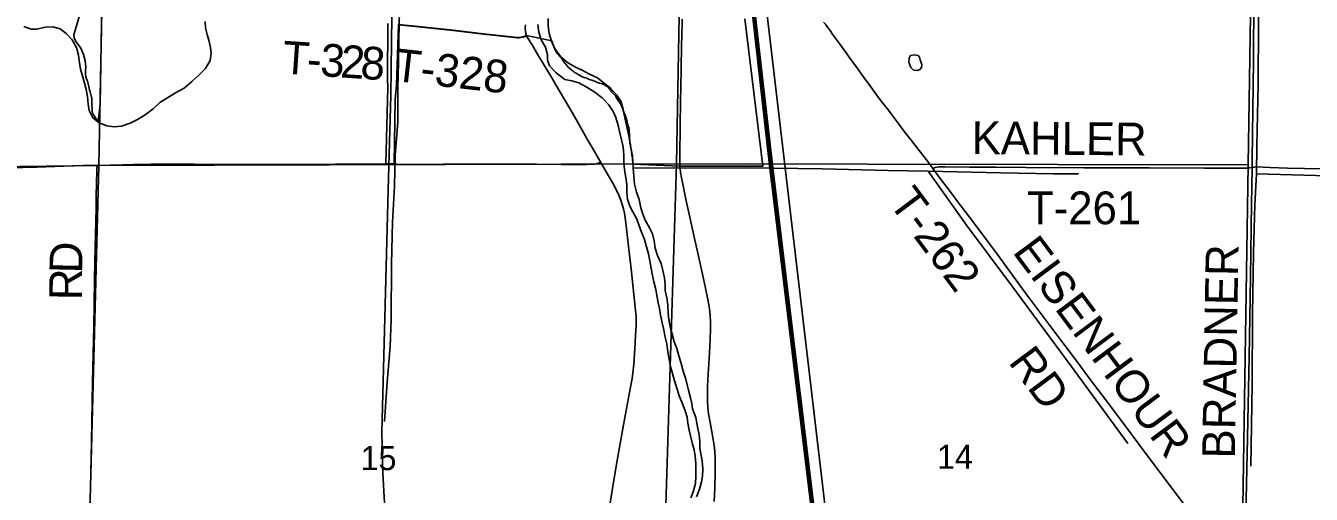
# Model space of a CAD drawing. Extents: x 0 to 34, y 0 to 22.
# Drawn here: x 3.939 to 6.172, y 15.963 to 16.776 of the extents above; entities that cross this region are included whole.
import ezdxf

# ---------------------------------------------------------------- set-up
doc = ezdxf.new("R2010")
doc.units = 0
for name, color, linetype in [('GM_X_Corporation', 7, 'Continuous'), ('GM_X_County_Road', 7, 'Continuous'), ('GM_X_Major_River', 7, 'Continuous'), ('GM_X_Minor_Lake', 7, 'Continuous'), ('GM_X_Minor_River', 7, 'Continuous'), ('GM_X_Rail_Line', 7, 'Continuous'), ('GM_X_Section', 7, 'Continuous'), ('GM_X_Section_Text', 7, 'Continuous'), ('GM_X_Township_Road', 7, 'Continuous'), ('GM_X_Township_Road_Text', 7, 'Continuous')]:
    doc.layers.add(name, color=color, linetype=linetype)

msp = doc.modelspace()

# ---------------------------------------------------------------- linework, layer by layer
at = {"layer": 'GM_X_Corporation'}
for points in [[(4.071, 16.8152), (4.0678, 16.6389), (4.0673, 16.6338), (4.0643, 16.6095), (4.0598, 16.6158), (4.0552, 16.6228), (4.0545, 16.6247), (4.054, 16.6272), (4.0539, 16.6297), (4.0537, 16.6409), (4.0532, 16.6505), (4.0531, 16.6519), (4.0504, 16.6611), (4.0493, 16.6649), (4.0458, 16.6802), (4.0454, 16.681), (4.0446, 16.6828), (4.0439, 16.685), (4.0436, 16.6857), (4.0432, 16.6872), (4.0431, 16.6879), (4.0428, 16.6891), (4.0426, 16.6913), (4.0425, 16.6929), (4.0425, 16.6948), (4.0426, 16.6967), (4.0427, 16.6974), (4.0429, 16.7043), (4.0419, 16.7148), (4.0391, 16.7258), (4.0342, 16.737), (4.0265, 16.7481), (4.0233, 16.753), (4.0226, 16.7547), (4.0222, 16.7599), (4.0326, 16.7955)], [(5.1883, 16.7876), (5.2193, 16.5319), (5.0752, 16.5321), (4.9943, 16.5359), (4.9931, 16.5431), (4.9928, 16.5475), (4.9928, 16.5514), (4.9921, 16.5538), (4.9916, 16.5566), (4.9904, 16.5611), (4.9893, 16.5668), (4.9893, 16.5689), (4.9884, 16.5718), (4.9871, 16.5956), (4.9866, 16.5986), (4.9845, 16.605), (4.9836, 16.6098), (4.9817, 16.6154), (4.9803, 16.6207), (4.9781, 16.6259), (4.9768, 16.6286), (4.9765, 16.6297), (4.9758, 16.6321), (4.973, 16.6386), (4.9726, 16.6399), (4.9712, 16.642), (4.9706, 16.6432), (4.9694, 16.6446), (4.9672, 16.6475), (4.9653, 16.6503), (4.9638, 16.6534), (4.9619, 16.656), (4.9586, 16.659), (4.957, 16.6607), (4.9563, 16.662), (4.9532, 16.6662), (4.9507, 16.669), (4.95, 16.6697), (4.947, 16.6712), (4.9465, 16.6716), (4.9459, 16.6721), (4.9437, 16.6737), (4.9428, 16.6742), (4.942, 16.6745), (4.9408, 16.675), (4.9383, 16.6757), (4.9358, 16.6763), (4.9306, 16.6782), (4.9285, 16.6791), (4.9224, 16.6814), (4.9178, 16.6827), (4.9136, 16.6846), (4.9091, 16.6858), (4.9056, 16.687), (4.9038, 16.6883), (4.8986, 16.6911), (4.8969, 16.6925), (4.8949, 16.6935), (4.8917, 16.6953), (4.8896, 16.6968), (4.882, 16.7031), (4.8734, 16.7133), (4.8706, 16.7177), (4.8683, 16.7213), (4.8677, 16.7218), (4.8668, 16.7226), (4.8656, 16.724), (4.8635, 16.7264), (4.8617, 16.7285), (4.8602, 16.7309), (4.8598, 16.7318), (4.859, 16.7337), (4.8577, 16.7365), (4.8566, 16.739), (4.8564, 16.7397), (4.8562, 16.7404), (4.8557, 16.7417), (4.8547, 16.7434), (4.8544, 16.744), (4.8539, 16.7468), (4.8535, 16.7477), (4.8532, 16.7484), (4.8532, 16.7488), (4.853, 16.7495), (4.8086, 16.759), (4.8059, 16.7576), (4.8028, 16.7565), (4.7987, 16.7559), (4.7956, 16.7555), (4.7925, 16.7556), (4.7878, 16.7559), (4.7338, 16.762), (4.6813, 16.7679), (4.6211, 16.7743), (4.5862, 16.7781), (4.5828, 16.6728), (4.5805, 16.6481), (4.5787, 16.536), (4.5643, 16.5361), (4.5678, 16.6686), (4.5674, 16.6831), (4.5681, 16.78)]]:
    msp.add_lwpolyline(points, dxfattribs=at)
at = {"layer": 'GM_X_County_Road'}
for points in [[(4.8088, 16.7585), (4.8076, 16.7623), (4.8068, 16.7665), (4.8066, 16.7698), (4.8066, 16.7728), (4.8072, 16.7774)], [(5.0755, 16.5315), (5.0754, 16.5372), (5.0752, 16.5474), (5.0758, 16.6049), (5.0764, 16.6422), (5.0773, 16.6997), (5.0783, 16.7433), (5.0786, 16.7573), (5.0794, 16.7837), (5.0794, 16.787)], [(4.9378, 16.5386), (4.9228, 16.5645), (4.9142, 16.5793), (4.8972, 16.6089), (4.8926, 16.617), (4.8857, 16.6291), (4.8731, 16.6505), (4.8597, 16.6733), (4.8527, 16.6854), (4.8465, 16.6961), (4.836, 16.7134), (4.8303, 16.7226), (4.8239, 16.7332), (4.8207, 16.7386), (4.8185, 16.7425), (4.816, 16.7465), (4.8143, 16.749), (4.812, 16.7525), (4.81, 16.7558), (4.8088, 16.7585)], [(4.9539, 15.9482), (4.9617, 15.9942), (4.967, 16.0248), (4.9713, 16.0509), (4.9777, 16.0861), (4.9845, 16.1212), (4.9897, 16.1487), (4.9923, 16.164), (4.9941, 16.1779), (4.9952, 16.1888), (4.9969, 16.2152), (4.9983, 16.2385), (4.9993, 16.2556), (4.9994, 16.2634), (4.9992, 16.2712), (4.9983, 16.2821), (4.9943, 16.3207), (4.9913, 16.3486), (4.9855, 16.398), (4.9826, 16.4242), (4.9809, 16.4382), (4.979, 16.4505), (4.9775, 16.4581), (4.9753, 16.4657), (4.9727, 16.4731), (4.9691, 16.4817), (4.9645, 16.4916), (4.9594, 16.5013), (4.9384, 16.5376), (4.9378, 16.5386)], [(5.1346, 15.95), (5.1359, 15.9732), (5.1368, 15.9996), (5.1369, 16.0136), (5.1366, 16.026), (5.136, 16.0368), (5.1348, 16.0475), (5.1325, 16.0613), (5.1277, 16.0873), (5.1253, 16.1026), (5.124, 16.1135), (5.1233, 16.1244), (5.1231, 16.1353), (5.1233, 16.1509), (5.1242, 16.1711), (5.1265, 16.2083), (5.1278, 16.2315), (5.1285, 16.2501), (5.1286, 16.2625), (5.1282, 16.2718), (5.1275, 16.2795), (5.1262, 16.2887), (5.1234, 16.3039), (5.1199, 16.3206), (5.1145, 16.3449), (5.1063, 16.3812), (5.0995, 16.4116), (5.0927, 16.4435), (5.0865, 16.4723), (5.081, 16.4982), (5.0781, 16.5119), (5.0765, 16.5211), (5.0756, 16.5289), (5.0755, 16.5315)]]:
    msp.add_lwpolyline(points, dxfattribs=at)
at = {"layer": 'GM_X_Major_River'}
for points in [[(4.2504, 16.7831), (4.2509, 16.7724), (4.254, 16.7606), (4.2568, 16.751), (4.2599, 16.738), (4.2608, 16.7285), (4.2593, 16.7157), (4.251, 16.7014), (4.2398, 16.6907), (4.2274, 16.6792), (4.2138, 16.6674), (4.1989, 16.6594), (4.1719, 16.6426), (4.1603, 16.6319), (4.146, 16.6212), (4.133, 16.6132), (4.1199, 16.6067), (4.105, 16.6017), (4.0921, 16.6002), (4.0793, 16.6024), (4.0665, 16.6076), (4.055, 16.6162), (4.0489, 16.6289), (4.0473, 16.64), (4.0457, 16.6529)], [(4.8285, 16.7778), (4.8305, 16.7645), (4.8343, 16.7515), (4.8416, 16.7384), (4.845, 16.7254), (4.8452, 16.7159), (4.8487, 16.7063), (4.8602, 16.6939), (4.8754, 16.6825), (4.8878, 16.6803), (4.8999, 16.6766), (4.9126, 16.6699), (4.926, 16.662), (4.9401, 16.651), (4.9512, 16.6393), (4.9596, 16.627)], [(5.0278, 16.4147), (5.0224, 16.4251), (5.0151, 16.4385), (5.0105, 16.4504), (5.0073, 16.46), (5.0043, 16.4741), (4.9997, 16.4871), (4.9962, 16.5009), (4.9951, 16.5149), (4.9943, 16.5294), (4.9935, 16.5423), (4.9918, 16.5518), (4.9905, 16.5613), (4.9889, 16.5716), (4.9866, 16.5846), (4.9835, 16.5983), (4.9815, 16.6086), (4.9784, 16.6216), (4.9764, 16.6334), (4.9727, 16.6451), (4.9652, 16.6557), (4.9546, 16.6677), (4.9412, 16.6778), (4.9323, 16.6853), (4.9184, 16.6917), (4.9053, 16.6989), (4.893, 16.7045), (4.8799, 16.712), (4.868, 16.7222), (4.8574, 16.7372), (4.8524, 16.7491), (4.8482, 16.7625), (4.8463, 16.7755), (4.8466, 16.7884)], [(4.0457, 16.6529), (4.0437, 16.6651), (4.0403, 16.6785), (4.0368, 16.6907), (4.0336, 16.7006), (4.0317, 16.7155), (4.0304, 16.725), (4.027, 16.738), (4.0194, 16.7515), (4.009, 16.7623), (3.9986, 16.7702), (3.9855, 16.7739), (3.9722, 16.7731), (3.9581, 16.77), (3.9479, 16.7699), (3.9355, 16.7747)], [(4.9596, 16.627), (4.9639, 16.6166), (4.9681, 16.6029), (4.9712, 16.5903), (4.9742, 16.5758), (4.9766, 16.5655), (4.9778, 16.5514), (4.9779, 16.5419), (4.9784, 16.5316), (4.9797, 16.5221), (4.9821, 16.5092), (4.9829, 16.4993), (4.9834, 16.4867), (4.9842, 16.475), (4.9881, 16.4627), (4.9935, 16.4531), (5.0004, 16.44), (5.004, 16.4305), (5.0089, 16.4174), (5.0136, 16.4052), (5.0174, 16.3922), (5.0205, 16.38), (5.0229, 16.3678), (5.0256, 16.3544), (5.0279, 16.3426), (5.0303, 16.3315), (5.0334, 16.3182), (5.0361, 16.3048), (5.0377, 16.2953), (5.0398, 16.2854), (5.0414, 16.2739), (5.0448, 16.2602), (5.0475, 16.248), (5.0492, 16.2377), (5.0526, 16.224), (5.0546, 16.2102), (5.0592, 16.1847)], [(5.104, 15.9586), (5.1092, 15.9717), (5.1129, 15.9842), (5.1147, 15.994), (5.1154, 16.0061), (5.1142, 16.0206), (5.1119, 16.0331), (5.1102, 16.043), (5.1098, 16.0552), (5.1089, 16.0662), (5.1062, 16.08), (5.1028, 16.096), (5.0975, 16.1109), (5.0959, 16.1204), (5.0935, 16.1304), (5.09, 16.1434), (5.088, 16.1529), (5.0856, 16.1624), (5.081, 16.1762), (5.0773, 16.1897), (5.0737, 16.203), (5.0702, 16.2159), (5.0656, 16.2271), (5.0621, 16.2404), (5.0583, 16.2534), (5.0559, 16.2663), (5.0551, 16.277), (5.0543, 16.2907), (5.0527, 16.3037), (5.0496, 16.3166), (5.0495, 16.3261), (5.0483, 16.3383), (5.0459, 16.3513), (5.0426, 16.3633), (5.0367, 16.3769), (5.0325, 16.3899), (5.0305, 16.4025), (5.0278, 16.4147)], [(5.0592, 16.1847), (5.0623, 16.1725), (5.0662, 16.1599), (5.0707, 16.1453), (5.0739, 16.1339), (5.0789, 16.1224), (5.0842, 16.1093), (5.0877, 16.0967), (5.0893, 16.0861), (5.0917, 16.0739), (5.0937, 16.0643), (5.0975, 16.0498), (5.0999, 16.0399), (5.1016, 16.0292), (5.1031, 16.0163), (5.1033, 16.0064), (5.1033, 15.9935), (5.1023, 15.9818), (5.0985, 15.967), (5.0941, 15.9565)]]:
    msp.add_lwpolyline(points, dxfattribs=at)
at = {"layer": 'GM_X_Minor_Lake'}
msp.add_line((5.4945, 16.7112), (5.4928, 16.7169), dxfattribs=at)
msp.add_lwpolyline([(5.4928, 16.7169), (5.4914, 16.7211), (5.4892, 16.7242), (5.4824, 16.7251), (5.4759, 16.7241), (5.4739, 16.7196), (5.473, 16.7125), (5.4765, 16.7033), (5.4813, 16.699), (5.4878, 16.6984), (5.4923, 16.6998), (5.4951, 16.7036), (5.4956, 16.7089), (5.4945, 16.7112)], dxfattribs=at)
at = {"layer": 'GM_X_Minor_River'}
for points in [[(5.9525, 17.4663), (5.9673, 17.3585), (5.9751, 17.3223), (5.9834, 17.2898), (5.9907, 17.2802), (5.9982, 17.2758), (6.0699, 17.2665), (6.0858, 17.2657), (6.0859, 17.1469), (6.0836, 16.9193), (6.0809, 16.7797), (6.0802, 16.6742), (6.0776, 16.568), (6.0771, 16.519), (6.0742, 16.4648), (6.0722, 16.3818), (6.0703, 16.2755), (6.0696, 16.1541), (6.0672, 16.0115)], [(4.5719, 17.0263), (4.5772, 16.9824), (4.5826, 16.9378), (4.5861, 16.8839), (4.5872, 16.8493), (4.5885, 16.8165), (4.5874, 16.7809), (4.587, 16.7468), (4.5863, 16.7126), (4.5853, 16.6664), (4.5854, 16.6087), (4.5805, 16.5511), (4.5796, 16.4973), (4.5762, 16.4351), (4.574, 16.3627), (4.5739, 16.2667), (4.5716, 16.2193), (4.5666, 16.1575), (4.5623, 16.089)], [(4.9943, 16.5294), (5.0848, 16.5287), (5.195, 16.5294), (5.3233, 16.5275), (5.4369, 16.5247), (5.5069, 16.5234), (5.6326, 16.5207), (5.7249, 16.5189), (5.7681, 16.5189)], [(5.5069, 16.5234), (5.5731, 16.4299), (5.6519, 16.3244), (5.7553, 16.1849), (5.8538, 16.0508)], [(6.0771, 16.519), (6.2625, 16.5138), (6.4116, 16.5101), (6.5645, 16.5061), (6.6962, 16.5021), (6.8086, 16.499), (6.9562, 16.4958), (7.0641, 16.4932), (7.0626, 16.3274), (7.06, 16.2367), (7.0568, 16.1389), (7.0545, 16.0319), (7.0522, 15.9219)]]:
    msp.add_lwpolyline(points, dxfattribs=at)
at = {"layer": 'GM_X_Rail_Line'}
for points in [[(5.533, 14.1), (5.4414, 14.8452), (5.2368, 16.5291), (5.1973, 16.873), (5.1794, 17.0253), (5.1537, 17.2322), (5.1303, 17.4189), (5.1198, 17.5024), (5.1038, 17.6379), (5.0605, 17.8802), (4.9539, 18.5048), (4.7781, 19.5207), (4.6486, 20.2766), (4.541, 20.9)], [(5.1575, 17.231), (5.1689, 17.2254), (5.1772, 17.2171), (5.4556, 14.8553)], [(4.562, 17.1188), (4.5796, 16.883), (4.5748, 16.7925), (4.5733, 16.6553), (4.5685, 16.4905), (4.5573, 16.0706), (4.559, 15.9996), (4.5639, 15.9172), (4.5639, 15.8252), (4.5607, 15.7154), (4.5448, 15.1679), (4.5209, 14.2861), (4.5155, 14.1)], [(5.3972, 15.1881), (5.3809, 15.3015), (5.2318, 16.5285), (5.1928, 16.873), (5.1831, 16.9698)], [(5.3721, 15.3935), (5.372, 15.3954), (5.2343, 16.5288), (5.2026, 16.8071)]]:
    msp.add_lwpolyline(points, dxfattribs=at)
at = {"layer": 'GM_X_Section'}
for points in [[(4.0852, 17.5486), (4.0656, 16.5335), (3.0627, 16.5204), (3.0931, 17.5206)], [(5.0874, 17.5326), (5.0695, 16.5364), (4.0656, 16.5335), (4.0852, 17.5486), (4.6502, 17.5462)], [(6.0785, 17.5378), (6.0628, 16.5344), (5.0695, 16.5364), (5.0874, 17.5326)], [(3.0627, 16.5204), (4.0656, 16.5335), (4.0396, 15.5284), (3.0319, 15.521)], [(4.0656, 16.5335), (5.0695, 16.5364), (5.0389, 15.5548), (4.0396, 15.5284)], [(5.0695, 16.5364), (6.0628, 16.5344), (6.0471, 15.5341), (5.0389, 15.5548)]]:
    msp.add_lwpolyline(points, close=True, dxfattribs=at)
at = {"layer": 'GM_X_Township_Road'}
for points in [[(6.0695, 16.5301), (6.0697, 16.5425), (6.0703, 16.5876), (6.0718, 16.715), (6.0721, 16.7477), (6.0726, 16.7927), (6.0727, 16.8129), (6.0731, 16.8502), (6.0735, 16.8844), (6.0741, 16.9311), (6.0747, 16.9699), (6.0773, 17.0771), (6.0782, 17.1206), (6.0788, 17.1548), (6.0798, 17.1844), (6.081, 17.2092), (6.0821, 17.2356), (6.083, 17.2589), (6.0841, 17.2868), (6.0847, 17.3055), (6.0865, 17.3769), (6.0872, 17.4033), (6.0873, 17.4152)], [(4.5864, 16.7776), (4.6213, 16.7738), (4.6815, 16.7673), (4.734, 16.7615), (4.7881, 16.7554), (4.7927, 16.755), (4.7958, 16.755), (4.7989, 16.7553), (4.803, 16.7559), (4.8061, 16.757), (4.8088, 16.7585)], [(5.3249, 16.7818), (5.3282, 16.7783), (5.332, 16.7732), (5.3376, 16.7656), (5.3402, 16.7618), (5.3521, 16.7454), (5.3611, 16.7327), (5.3692, 16.7214), (5.384, 16.7014), (5.3968, 16.6838), (5.404, 16.6737), (5.4167, 16.656), (5.4251, 16.6449), (5.4376, 16.6291), (5.4442, 16.6204), (5.4526, 16.6092), (5.4658, 16.592), (5.4772, 16.5772), (5.4933, 16.5563), (5.5095, 16.5354), (5.5151, 16.5279)], [(3.2694, 16.5184), (3.2739, 16.5184), (3.2928, 16.5186), (3.3736, 16.5193), (3.4233, 16.5201), (3.4699, 16.5208), (3.5445, 16.5219), (3.5943, 16.5228), (3.6346, 16.5232), (3.6657, 16.5237), (3.7061, 16.5246), (3.7434, 16.5254), (3.8304, 16.5272), (3.8553, 16.5277), (3.9081, 16.5292), (3.9578, 16.5307), (3.9889, 16.5315), (4.0386, 16.5331), (4.0603, 16.5335), (4.0626, 16.5336)], [(4.0423, 15.5293), (4.0425, 15.5415), (4.0434, 15.5974), (4.044, 15.6301), (4.0452, 15.7203), (4.0465, 15.8042), (4.0473, 15.8369), (4.0497, 15.924), (4.051, 15.9737), (4.0528, 16.0545), (4.0549, 16.1572), (4.0567, 16.2551), (4.0575, 16.2909), (4.0583, 16.3375), (4.0594, 16.3919), (4.0599, 16.4137), (4.0603, 16.4355), (4.0608, 16.4603), (4.0612, 16.4805), (4.0616, 16.5023), (4.0623, 16.5241), (4.0624, 16.5272), (4.0626, 16.5336)], [(4.0626, 16.5336), (4.0852, 16.534), (4.1069, 16.5344), (4.1256, 16.5349), (4.1566, 16.5355), (4.1783, 16.5356), (4.2312, 16.5355), (4.2964, 16.5353), (4.3431, 16.5351), (4.3835, 16.5351), (4.4083, 16.5352), (4.4767, 16.5354), (4.5635, 16.5355)], [(4.5635, 16.5355), (4.5645, 16.5355), (4.5789, 16.5354)], [(4.5789, 16.5354), (4.5837, 16.5354), (4.6303, 16.5353), (4.6645, 16.5354), (4.7328, 16.5355), (4.7949, 16.5355), (4.826, 16.5354), (4.8695, 16.5353), (4.913, 16.5353), (4.9224, 16.5355), (4.9272, 16.5359), (4.9318, 16.5369), (4.9378, 16.5386)], [(5.5151, 16.5279), (5.5187, 16.5298), (5.5224, 16.5307), (5.5255, 16.5309), (5.5364, 16.5309), (5.5784, 16.5306), (5.625, 16.5302), (5.6763, 16.5301), (5.7773, 16.5294), (5.8908, 16.529), (5.9871, 16.5287), (6.04, 16.5286), (6.054, 16.5288), (6.0617, 16.5287), (6.0652, 16.5291), (6.0688, 16.53), (6.0695, 16.5301)], [(5.5151, 16.5279), (5.5244, 16.5155), (5.5467, 16.4857), (5.558, 16.4708), (5.5767, 16.446), (5.5861, 16.4336), (5.6132, 16.3976), (5.6271, 16.3789), (5.675, 16.3138), (5.741, 16.2255), (5.7504, 16.2131), (5.7726, 16.1831), (5.7885, 16.1621), (5.8092, 16.1348), (5.853, 16.0764), (5.8846, 16.0341), (5.9323, 15.9708), (5.9585, 15.9361)], [(6.056, 15.8095), (6.056, 15.8106), (6.0568, 15.8355), (6.0579, 15.8914), (6.0596, 15.9535), (6.0617, 16.0608), (6.0625, 16.0903), (6.0647, 16.2006), (6.067, 16.3389), (6.0681, 16.426), (6.0688, 16.4679), (6.0691, 16.4959), (6.0695, 16.5301)], [(6.0695, 16.5301), (6.073, 16.5307), (6.0771, 16.5308), (6.1004, 16.5299), (6.1314, 16.5288), (6.1905, 16.5275), (6.2868, 16.525), (6.3148, 16.5243), (6.3474, 16.5236), (6.4438, 16.5211), (6.481, 16.5199), (6.5867, 16.5171), (6.6582, 16.515), (6.7234, 16.5133), (6.7949, 16.5112), (6.8275, 16.5102), (6.8679, 16.5091), (6.9984, 16.5051), (7.0652, 16.5028), (7.0714, 16.5029), (7.0781, 16.503)]]:
    msp.add_lwpolyline(points, dxfattribs=at)

# ---------------------------------------------------------------- texts
at = {"layer": 'GM_X_Section_Text'}
for s, p in [('15', (4.5205, 16.0047)), ('14', (5.5222, 16.007))]:
    msp.add_text(s, height=0.04186, rotation=0, dxfattribs=at).set_placement(p)
at = {"layer": 'GM_X_Township_Road_Text'}
for s, height, rotation, p in [('T', 0.0568, 356.0799, (4.3834, 16.6932)), ('3', 0.0568, 356.0863, (4.4491, 16.6887)), ('2', 0.0568, 356.1312, (4.4841, 16.6863)), ('8', 0.0568, 356.3202, (4.5192, 16.6839)), ('T-328', 0.05682, 353.5679, (4.5763, 16.6803)), ('-', 0.0568, 356.0629, (4.4258, 16.6903)), ('KAHLER', 0.05682, 359.4938, (5.5822, 16.5533)), ('T-262', 0.05682, 306.76, (5.4368, 16.4686)), ('T-261', 0.05682, 0, (5.6784, 16.4314)), ('D', 0.0568, 88.816, (4.0365, 16.3458)), ('EISENHOUR', 0.05682, 306.7256, (5.6522, 16.3833)), ('BRADNER', 0.05682, 88.9919, (6.0396, 16.0245)), ('R', 0.0568, 89.4809, (4.0361, 16.2994)), ('RD', 0.05682, 306.6892, (5.6448, 16.192))]:
    msp.add_text(s, height=height, rotation=rotation, dxfattribs=at).set_placement(p)

doc.saveas('drawing.dxf')
